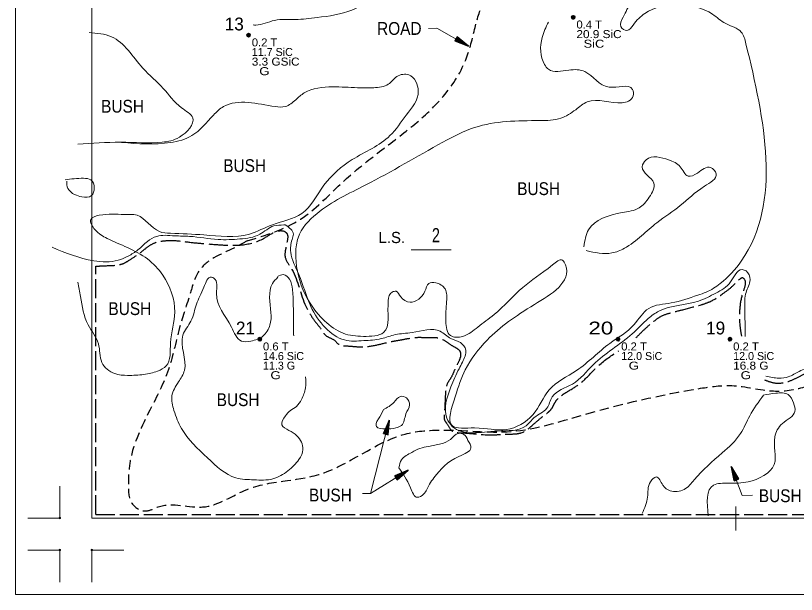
# Model space of a CAD drawing. Extents: x -496 to 480, y -450 to 700.
# Drawn here: x -450 to 37.7, y -450 to -88.3 of the extents above; entities that cross this region are included whole.
import ezdxf
from ezdxf.enums import TextEntityAlignment as Align

# ---------------------------------------------------------------- set-up
doc = ezdxf.new("R2010")
doc.units = 0
doc.header["$LTSCALE"] = 2
doc.header["$PDMODE"] = 32
doc.header["$PDSIZE"] = 1
doc.linetypes.add('LONG_DASHED', pattern=[7.5, 6, -1.5])
doc.linetypes.add('MEDIUM_DASHED', pattern=[4.5, 3, -1.5])
for name, color, linetype, lineweight in [('1', 7, 'Continuous', 13), ('2', 7, 'Continuous', 35), ('3', 7, 'Continuous', 13), ('4', 7, 'Continuous', 25)]:
    doc.layers.add(name, color=color, linetype=linetype, lineweight=lineweight)

msp = doc.modelspace()

# ---------------------------------------------------------------- linework, layer by layer
at = {"layer": '1'}
for p, q in [((-402.391, 402.339), (-402.391, -402.333)), ((-202.998, -234.618), (-177.998, -234.618)), ((-422.391, -402.333), (-422.391, -382.333)), ((-0.017, -395.027), (-0.017, -410.027)), ((-422.391, -402.333), (-442.391, -402.333)), ((-402.391, -402.333), (402.281, -402.333)), ((-422.391, -422.333), (-442.391, -422.333)), ((-422.391, -422.333), (-422.391, -442.333)), ((-402.391, -422.333), (-402.391, -442.333)), ((-450.017, -450.027), (449.983, -450.027))]:
    msp.add_line(p, q, dxfattribs=at)
for points in [[(449.983, -450.027), (449.983, 399.973), (449.983, 699.973), (-450.017, 699.973), (-450.017, 49.973), (-450.017, -450.027)], [(-402.391, -422.333), (-382.391, -422.333), (-402.391, -422.333)]]:
    msp.add_lwpolyline(points, dxfattribs=at)
for p in [(-422.391, -402.333), (-422.391, -422.333), (-402.391, -422.333)]:
    msp.add_point(p, dxfattribs=at)
at = {"layer": '2', "linetype": 'LONG_DASHED', "lineweight": 25}
for q in [(-400, -245), (302.281, -400)]:
    msp.add_line((-400, -400), q, dxfattribs=at)
at = {"layer": '2'}
for centre in [(-101.678, -89.394), (-304.484, -100.57), (-297.491, -290.569), (-73.705, -290.569), (-3.772, -290.569)]:
    msp.add_circle(centre, 1, dxfattribs=at)
for points in [[(-101.689, -88.507), (-100.958, -88.911), (-100.807, -89.759), (-101.492, -90.287), (-102.301, -90.057), (-102.587, -89.299), (-102.34, -88.737), (-101.767, -88.568), (-101.093, -89.063), (-101.11, -89.804), (-101.627, -90.062), (-102.149, -89.894), (-102.374, -89.248), (-101.79, -88.782), (-101.352, -89.315), (-101.391, -89.799), (-102.02, -89.664), (-101.874, -89.029), (-101.582, -89.579)], [(-304.495, -99.683), (-303.765, -100.087), (-303.613, -100.936), (-304.298, -101.464), (-305.107, -101.233), (-305.394, -100.475), (-305.147, -99.913), (-304.574, -99.745), (-303.9, -100.239), (-303.916, -100.981), (-304.433, -101.239), (-304.956, -101.07), (-305.18, -100.424), (-304.596, -99.958), (-304.158, -100.492), (-304.197, -100.975), (-304.826, -100.84), (-304.68, -100.205), (-304.388, -100.756)], [(-297.502, -289.682), (-296.772, -290.086), (-296.62, -290.935), (-297.305, -291.463), (-298.114, -291.232), (-298.401, -290.474), (-298.153, -289.912), (-297.58, -289.744), (-296.906, -290.238), (-296.923, -290.98), (-297.44, -291.238), (-297.962, -291.069), (-298.187, -290.423), (-297.603, -289.957), (-297.165, -290.491), (-297.204, -290.974), (-297.833, -290.839), (-297.687, -290.204), (-297.395, -290.755)], [(-73.715, -289.682), (-72.985, -290.086), (-72.834, -290.935), (-73.519, -291.463), (-74.328, -291.232), (-74.614, -290.474), (-74.367, -289.912), (-73.794, -289.744), (-73.12, -290.238), (-73.137, -290.98), (-73.654, -291.238), (-74.176, -291.069), (-74.401, -290.423), (-73.817, -289.957), (-73.378, -290.491), (-73.418, -290.974), (-74.047, -290.839), (-73.901, -290.204), (-73.609, -290.755)], [(-3.782, -289.682), (-3.052, -290.086), (-2.9, -290.935), (-3.586, -291.463), (-4.394, -291.232), (-4.681, -290.474), (-4.434, -289.912), (-3.861, -289.744), (-3.187, -290.238), (-3.204, -290.98), (-3.72, -291.238), (-4.243, -291.069), (-4.467, -290.423), (-3.883, -289.957), (-3.445, -290.491), (-3.485, -290.974), (-4.114, -290.839), (-3.968, -290.204), (-3.675, -290.755)]]:
    msp.add_spline(points, degree=3, dxfattribs=at)
at = {"layer": '2', "linetype": 'LONG_DASHED', "lineweight": 25}
for points in [[(-400, -245), (-395.731, -244.712), (-388.818, -244.425), (-382.77, -243.274), (-378.737, -240.972), (-372.689, -236.944), (-368.656, -233.78), (-363.76, -230.615), (-357.999, -229.177), (-351.374, -228.889), (-340.429, -230.04), (-330.924, -230.903), (-318.539, -231.766), (-307.593, -231.478), (-294.344, -227.163), (-286.855, -223.135), (-282.247, -223.135), (-280.518, -224.573), (-280.23, -228.601), (-281.382, -234.355), (-281.67, -238.958), (-278.214, -245.575), (-269.285, -268.591), (-265.829, -275.208), (-262.66, -279.811), (-258.916, -284.702), (-256.324, -288.155), (-251.139, -291.032), (-247.395, -294.196), (-243.074, -294.772), (-234.721, -295.347), (-224.64, -294.196), (-215.999, -292.182), (-209.662, -291.032), (-205.054, -290.169), (-198.141, -289.305)], [(17.819, -315.951), (23.775, -317.83), (30.672, -317.517), (37.256, -315.012), (43.526, -311.88), (48.855, -308.749), (52.304, -305.931), (56.066, -299.042), (58.887, -287.142), (62.649, -274.304), (67.979, -258.647), (71.427, -251.132), (73.935, -246.122), (76.13, -243.93), (80.519, -242.364), (91.491, -237.667), (104.031, -231.717), (113.75, -226.394)], [(-62.437, -289.648), (-57.107, -284.324), (-50.837, -279.001), (-46.762, -276.183), (-40.492, -273.991), (-33.281, -272.112), (-21.682, -268.981), (-16.353, -267.102), (-8.202, -262.092), (-2.559, -257.708), (2.771, -252.697), (4.025, -252.071), (5.279, -253.324), (4.652, -260.213), (2.457, -270.233), (2.457, -282.445), (3.398, -288.708)], [(-198.141, -289.305), (-192.796, -289.474), (-188.165, -289.474), (-184.306, -290.245), (-179.29, -293.328), (-174.659, -296.027)], [(-174.659, -296.027), (-172.678, -297.775), (-172.039, -299.689), (-172.891, -303.732), (-175.447, -308.838), (-177.79, -314.156), (-180.346, -318.411), (-181.411, -323.517), (-181.837, -331.389), (-182.263, -337.559), (-182.05, -341.175), (-180.559, -343.303), (-177.151, -347.983), (-171.613, -349.047), (-151.805, -350.324), (-144.137, -349.898), (-137.534, -349.685), (-134.126, -349.047), (-126.245, -343.516), (-121.772, -339.686), (-117.725, -336.495), (-115.17, -333.942), (-113.466, -330.751), (-110.91, -327.347), (-102.39, -321.602), (-95.148, -316.284), (-85.776, -306.923), (-73.21, -297.775)]]:
    msp.add_spline(points, degree=3, dxfattribs=at)
at = {"layer": '3'}
for points in [[(-301.554, -94.191), (-299.967, -94.246), (-288.193, -91.306), (-275.242, -90.718), (-261.702, -89.542), (-239.921, -84.838), (-209.898, -60.73), (-168.69, -28.977), (-109.821, 18.063), (-99.814, 19.239), (-92.749, 16.887), (-83.919, 18.651), (-72.145, 23.355), (-59.783, 36.291), (-50.295, 42.403)], [(-36.052, -20.014), (-31.68, -21.469), (-32.166, -28.746), (-36.052, -41.359), (-52.565, -64.16), (-61.793, -74.833), (-68.107, -84.535), (-70.535, -89.387), (-71.992, -95.208), (-68.107, -97.634), (-64.221, -94.238), (-56.936, -86.961), (-14.681, -87.446), (-6.425, -93.268), (3.289, -98.604), (6.203, -105.881), (3.289, -241.716), (-9.824, -255.784), (-18.567, -261.121), (-23.909, -263.061), (-40.423, -267.912), (-54.508, -271.308), (-63.736, -281.496), (-78.792, -293.139), (-99.676, -310.118), (-116.675, -322.246), (-126.875, -337.77), (-143.388, -346.987), (-163.301, -346.017), (-177.386, -344.562), (-175.443, -326.612), (-169.13, -309.633), (-155.53, -291.198), (-125.903, -268.883), (-106.476, -244.141), (-108.419, -241.23), (-114.733, -244.141), (-133.189, -258.21), (-151.159, -275.189), (-161.359, -282.951), (-170.587, -288.773), (-178.358, -288.287), (-181.272, -279.555), (-180.786, -266.942), (-181.757, -259.18), (-187.586, -255.299), (-191.957, -255.784), (-194.385, -260.635), (-203.613, -267.427), (-209.442, -264.031), (-212.356, -260.635), (-214.784, -261.121), (-217.212, -266.457), (-220.127, -286.347), (-232.754, -288.773), (-245.382, -286.832), (-257.039, -279.07), (-275.009, -236.379), (-273.552, -227.162), (-261.896, -212.123), (-231.297, -194.173), (-183.214, -167.492), (-163.301, -158.274), (-122.504, -153.908), (-109.39, -152.453), (-100.162, -147.116), (-92.877, -142.265), (-71.021, -142.75), (-67.135, -141.78), (-64.221, -138.384), (-64.707, -134.503), (-79.278, -133.048), (-94.334, -123.345), (-104.533, -122.375), (-117.161, -121.89), (-119.59, -118.979), (-121.047, -102), (-117.209, -92.358)], [(-404.157, -98.96), (-390.188, -101.497), (-370.504, -121.158), (-357.804, -133.843), (-346.375, -145.893), (-339.39, -152.236), (-347.645, -164.286), (-358.439, -167.457), (-384.473, -167.457), (-411.142, -168.726)], [(-383.799, -167.626), (-353.268, -167.626), (-339.877, -163.346), (-326.486, -150.506), (-320.058, -145.156), (-287.92, -145.156), (-281.493, -145.156), (-275.065, -140.876), (-269.709, -136.595), (-252.033, -132.85), (-236.5, -133.385), (-226.323, -133.385), (-217.217, -131.245), (-211.861, -126.43), (-204.362, -125.36), (-198.47, -135.525), (-205.969, -150.506), (-216.146, -163.346), (-239.713, -178.327), (-257.389, -194.377), (-271.316, -212.032), (-289.527, -218.988), (-303.989, -224.873), (-332.378, -225.408), (-353.268, -224.338), (-360.231, -223.268), (-374.157, -213.102), (-382.192, -212.567), (-397.725, -213.102), (-403.082, -215.777), (-400.404, -222.198), (-392.905, -227.548), (-367.73, -240.388), (-358.088, -250.553), (-350.59, -273.559), (-353.268, -292.819), (-355.946, -307.265), (-361.302, -310.475), (-369.872, -312.615), (-380.049, -313.15), (-388.084, -312.08), (-396.118, -305.125), (-398.261, -293.354), (-404.689, -281.584), (-409.509, -263.929), (-411.116, -254.833)], [(-95.011, -232.795), (-92.097, -222.123), (-71.212, -211.45), (-60.527, -208.539), (-54.213, -201.747), (-51.299, -193.015), (-58.584, -182.828), (-56.156, -178.462), (-42.071, -178.462), (-34.786, -182.828), (-29.929, -188.649), (-24.101, -186.709), (-15.844, -183.313), (-12.444, -187.194), (-19.73, -194.956), (-34.786, -207.084), (-49.356, -217.757), (-59.07, -226.004), (-69.755, -233.766), (-77.526, -236.676), (-93.554, -235.221)], [(-419.118, -191.044), (-407.544, -189.993), (-402.984, -191.044), (-400.879, -195.948), (-402.633, -200.853), (-408.596, -201.554), (-413.156, -200.153), (-417.365, -196.299), (-418.066, -191.744)], [(-281.53, -219.059), (-282.544, -219.139), (-288.722, -219.789), (-297.5, -224.984), (-309.854, -227.907), (-323.509, -228.232), (-341.39, -226.283), (-350.493, -225.959), (-356.671, -225.634), (-361.872, -226.283), (-367.725, -229.531), (-373.577, -234.727), (-379.754, -238.624), (-385.931, -241.221), (-401.211, -241.546), (-427.221, -233.103)], [(5.763, -288.787), (5.449, -270.949), (6.287, -261.324), (8.8, -253.373), (6.287, -247.933), (3.773, -247.096), (-3.349, -254.629), (-12.566, -261.742), (-23.459, -266.764), (-48.177, -273.041), (-54.88, -277.644), (-64.934, -287.269), (-89.233, -306.518), (-102.221, -318.653), (-114.789, -326.604), (-118.141, -333.718), (-126.101, -339.576), (-131.128, -344.598), (-149.143, -347.945), (-177.212, -345.016), (-180.564, -339.995), (-178.05, -320.327), (-173.023, -309.029), (-170.928, -304.844), (-168.833, -297.312), (-172.185, -292.709), (-178.05, -290.198), (-184.753, -285.595), (-202.349, -286.432), (-212.823, -287.687), (-221.62, -290.198), (-232.513, -291.453), (-244.663, -291.035), (-256.393, -283.502), (-265.61, -270.112), (-273.151, -250.025), (-278.178, -236.216), (-277.34, -228.265), (-276.503, -224.918), (-281.53, -219.059)], [(69.084, -246.56), (60.331, -268.438), (57.398, -281.829), (55.303, -289.779), (51.952, -298.567), (47.343, -306.518), (39.383, -310.702), (32.68, -314.05), (26.815, -314.887), (18.669, -313.712)], [(-268.835, -314.089), (-268.956, -321.03), (-271.455, -328.206), (-274.578, -332.574), (-278.326, -335.07), (-281.45, -338.501), (-283.636, -344.117), (-279.263, -347.549), (-274.266, -350.981), (-270.518, -359.404), (-273.016, -365.644), (-279.888, -372.82), (-289.258, -377.811), (-301.127, -378.435), (-312.372, -377.187), (-330.175, -364.708), (-346.417, -346.301), (-351.103, -335.07), (-352.352, -326.022), (-348.291, -317.287), (-344.543, -310.111), (-345.48, -287.96), (-340.483, -279.225), (-337.047, -268.617), (-332.362, -258.01), (-327.677, -251.77), (-326.115, -252.394), (-324.553, -261.754), (-315.183, -282.969), (-308.936, -291.704), (-303.002, -291.704), (-295.505, -288.584), (-291.132, -281.721), (-290.508, -273.921), (-289.571, -255.826), (-286.135, -251.77)], [(-286.447, -251.458), (-282.699, -250.21), (-278.951, -253.018), (-277.077, -259.57), (-276.452, -279.225), (-276.3, -288.472)], [(-220.23, -334.446), (-213.671, -330.078), (-209.611, -326.334), (-205.862, -327.27), (-203.988, -331.638), (-206.175, -337.254), (-208.986, -344.429), (-212.422, -345.989), (-218.981, -346.613), (-224.603, -345.053), (-224.603, -342.557), (-223.354, -340.373), (-220.23, -334.758)], [(-58.589, -399.474), (-55.278, -389.252), (-53.472, -379.63), (-49.86, -376.624), (-45.646, -381.735), (-41.13, -385.343), (-32.401, -384.441), (-26.08, -378.428), (-8.621, -361.591), (2.818, -349.564), (8.537, -338.439), (17.266, -325.511)], [(16.965, -325.511), (24.792, -324.308), (32.618, -325.21), (35.929, -330.321), (36.832, -335.733), (29.006, -343.25), (24.19, -351.669), (23.889, -368.807), (7.634, -379.63), (-4.708, -380.532), (-14.039, -381.735), (-17.35, -400.978)], [(-210.548, -370.636), (-208.986, -365.956), (-202.427, -361.276), (-197.429, -358.78), (-192.119, -357.532), (-184.311, -355.972), (-178.376, -353.165), (-173.379, -349.421), (-169.943, -350.045), (-167.444, -353.789), (-165.57, -358.468), (-173.066, -363.772), (-188.684, -377.187), (-191.495, -381.243), (-195.243, -387.483), (-198.991, -389.355), (-203.364, -383.427), (-210.548, -370.948)]]:
    msp.add_spline(points, degree=3, dxfattribs=at)
at = {"layer": '3', "linetype": 'MEDIUM_DASHED', "lineweight": 25}
for points in [[(-305.408, -229.098), (-272.087, -215.55), (-246.937, -193.569), (-226.728, -176.523), (-204.722, -159.477), (-184.063, -140.188), (-168.793, -115.965), (-162.955, -95.778), (-157.117, -78.732), (-138.255, -57.649), (-121.189, -43.294), (-105.47, -33.426), (-85.26, -28.94), (-69.991, -24.454), (-49.332, -17.725), (-36.308, -10.099)], [(-305.408, -229.098), (-312.128, -232.799), (-334.893, -247.116), (-340.795, -261.433), (-347.54, -283.329), (-355.129, -311.121), (-366.933, -336.386), (-378.737, -368.389), (-379.58, -381.864), (-377.05, -393.654), (-368.619, -397.865), (-361.031, -395.338), (-332.363, -395.338), (-305.383, -384.39), (-260.696, -375.126), (-206.734, -349.861), (-185.655, -347.334), (-140.125, -348.177), (-96.281, -338.071), (-22.084, -321.227), (-2.691, -319.543), (23.446, -322.911), (42.839, -320.385), (58.016, -315.332), (85.84, -311.963), (99.951, -310.092)]]:
    msp.add_spline(points, degree=3, dxfattribs=at)
at = {"layer": '4', "lineweight": 13}
msp.add_line((-228.234, -387.079), (-204.767, -372.454), dxfattribs=at)
for points in [[(-192.018, -96.301), (-186.829, -96.134), (-167.078, -107.336)], [(-233.249, -387.079), (-228.234, -387.079), (-216.601, -341.201)], [(10.237, -388.068), (3.87, -388.223), (-2.964, -370.074)]]:
    msp.add_lwpolyline(points, dxfattribs=at)
at = {"layer": '4'}
for points in [[(-167.078, -107.336), (-174.166, -101.591), (-175.646, -104.201)], [(-216.601, -341.201), (-220.267, -349.556), (-217.359, -350.294)], [(-2.964, -370.074), (-1.196, -379.025), (1.611, -377.968)], [(-204.767, -372.454), (-213.199, -375.941), (-211.612, -378.487)]]:
    msp.add_lwpolyline(points, close=True, dxfattribs=at)
for points in [[(-174.146, -101.705), (-167.452, -107.123), (-175.479, -104.154), (-174.182, -101.834), (-167.932, -106.851), (-175.289, -104.114), (-174.126, -101.996), (-168.44, -106.563), (-175.082, -104.044), (-174.121, -102.184), (-169.009, -106.222), (-174.854, -104.005), (-174.059, -102.407), (-169.693, -105.814), (-174.631, -103.908), (-174.015, -102.656), (-170.432, -105.377), (-174.328, -103.8), (-173.933, -102.906), (-171.227, -104.87), (-174.007, -103.759), (-173.817, -103.195), (-172.208, -104.332), (-173.618, -103.664)], [(-220.163, -349.507), (-216.708, -341.618), (-217.449, -350.145), (-220.029, -349.507), (-216.843, -342.154), (-217.537, -349.972), (-219.888, -349.41), (-216.987, -342.719), (-217.66, -349.79), (-219.707, -349.355), (-217.165, -343.359), (-217.757, -349.581), (-219.509, -349.237), (-217.378, -344.126), (-217.91, -349.392), (-219.28, -349.128), (-217.604, -344.953), (-218.094, -349.128), (-219.061, -348.983), (-217.882, -345.854), (-218.219, -348.83), (-218.813, -348.796), (-218.142, -346.942), (-218.413, -348.479)], [(-1.139, -378.925), (-2.813, -370.477), (1.453, -377.897), (-1.029, -378.848), (-2.618, -370.994), (1.282, -377.806), (-0.968, -378.689), (-2.412, -371.54), (1.077, -377.727), (-0.851, -378.54), (-2.193, -372.167), (0.877, -377.611), (-0.756, -378.33), (-1.929, -372.917), (0.644, -377.543), (-0.631, -378.11), (-1.641, -373.726), (0.342, -377.432), (-0.534, -377.866), (-1.355, -374.624), (0.069, -377.258), (-0.437, -377.57), (-0.946, -375.666), (-0.29, -377.082)], [(-213.09, -375.978), (-205.133, -372.681), (-211.574, -378.318), (-212.993, -376.071), (-205.602, -372.973), (-211.518, -378.132), (-212.824, -376.099), (-206.097, -373.282), (-211.48, -377.916), (-212.656, -376.184), (-206.668, -373.62), (-211.406, -377.698), (-212.431, -376.237), (-207.353, -374.026), (-211.385, -377.455), (-212.191, -376.316), (-208.089, -374.466), (-211.335, -377.138), (-211.932, -376.364), (-208.914, -374.923), (-211.218, -376.836), (-211.623, -376.4), (-209.856, -375.528), (-211.116, -376.449)]]:
    msp.add_lwpolyline(points, dxfattribs=at)

# ---------------------------------------------------------------- texts
at = {"layer": '1'}
msp.add_text('L.S.', height=7, dxfattribs=at).set_placement((-215.009, -230.48), align=Align.CENTER)
at = {"layer": '1', "width": 0.75}
msp.add_text('2', height=8.89, dxfattribs=at).set_placement((-187.46, -230.008), align=Align.CENTER)
at = {"layer": '2'}
for s, p in [(' 13', (-307.485, -97.57)), (' 21', (-300.491, -287.569)), (' 19', (-6.772, -287.569))]:
    msp.add_text(s, height=8, dxfattribs=at).set_placement(p, align=Align.RIGHT)
for s, width, p in [('0.4 T      ', 1.05, (-99.678, -96.394)), ('20.9 SiC   ', 1.1, (-99.678, -102.394)), ('0.2 T      ', 1.05, (-302.484, -107.57)), ('  SiC      ', 1.2, (-99.678, -108.394)), ('3.3 GSiC   ', 1.1, (-302.484, -119.57)), ('  G        ', 1.25, (-302.484, -125.57)), ('0.6 T      ', 1.05, (-295.491, -297.569)), ('0.2 T      ', 1.05, (-71.705, -297.569)), ('0.2 T      ', 1.05, (-1.772, -297.569)), ('  G        ', 1.25, (-71.705, -309.569)), ('16.8 G     ', 1.1, (-1.772, -309.569)), ('  G        ', 1.25, (-295.491, -315.569)), ('  G        ', 1.25, (-1.772, -315.569))]:
    msp.add_text(s, height=5, dxfattribs=dict(at, width=width)).set_placement(p)
for s, p in [('11.7 SiC   ', (-302.484, -113.57)), ('14.6 SiC   ', (-295.491, -303.569)), ('12.0 SiC   ', (-71.705, -303.569)), ('12.0 SiC   ', (-1.772, -303.569)), ('11.3 G     ', (-295.491, -309.569))]:
    msp.add_text(s, height=5, dxfattribs=at).set_placement(p)
at = {"layer": '2', "width": 1.3}
msp.add_text(' 20', height=8, dxfattribs=at).set_placement((-76.705, -287.569), align=Align.RIGHT)
at = {"layer": '4', "width": 0.9}
for s, p in [('ROAD', (-210.319, -100.375)), ('BUSH', (-383.228, -148.971)), ('BUSH', (-306.942, -186.074)), ('BUSH', (-123.303, -200.484)), ('BUSH', (-378.661, -275.461)), ('BUSH', (-311.026, -332.356)), ('BUSH', (-253.382, -391.942)), ('BUSH', (27.629, -392.383))]:
    msp.add_text(s, height=8, dxfattribs=at).set_placement(p, align=Align.CENTER)

doc.saveas('drawing.dxf')
